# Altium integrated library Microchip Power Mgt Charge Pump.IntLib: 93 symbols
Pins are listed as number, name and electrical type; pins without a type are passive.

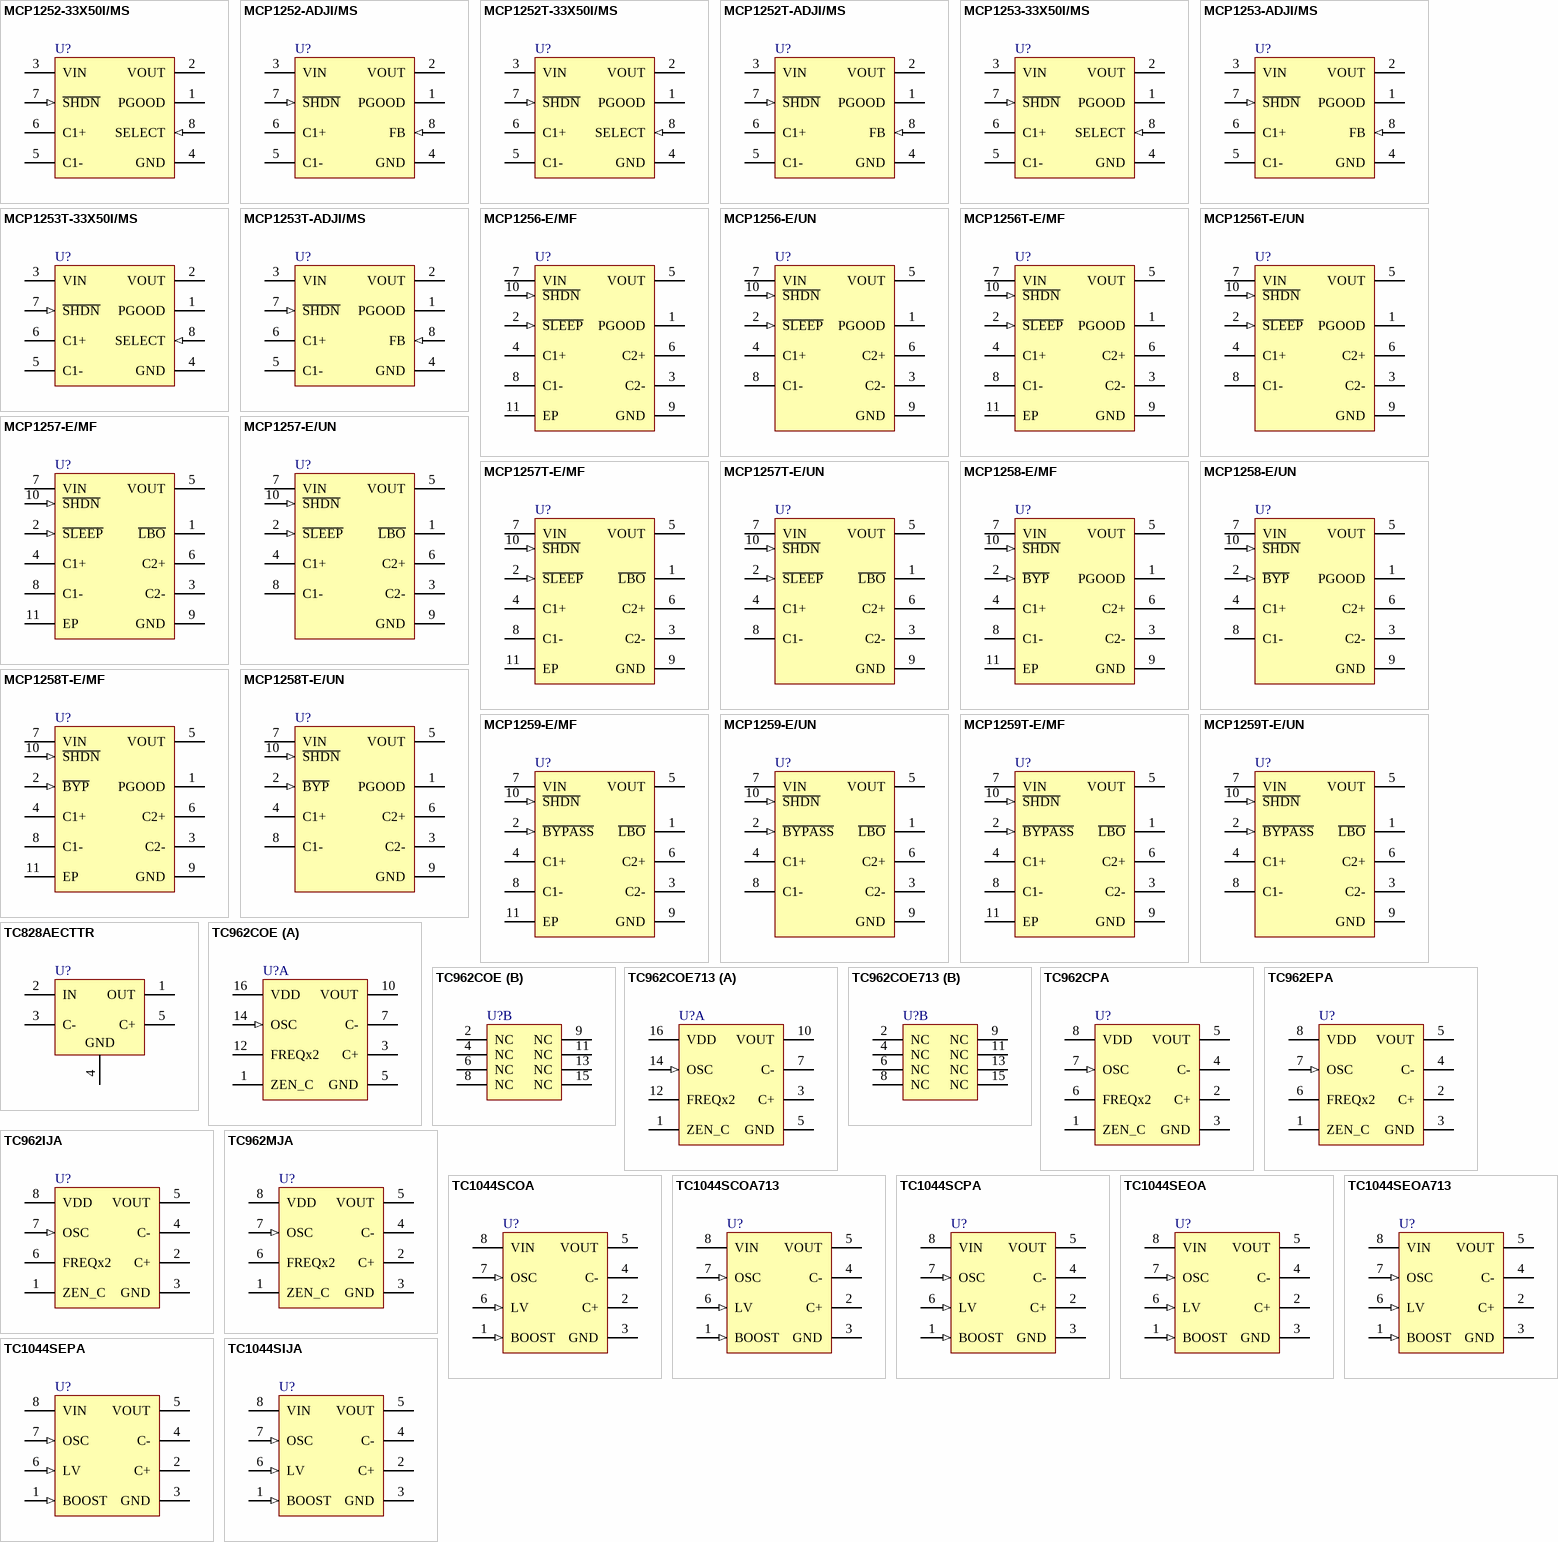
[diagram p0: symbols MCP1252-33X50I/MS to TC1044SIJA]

## MCP1252-33X50I/MS
designator U?
Low Noise, Positive-Regulated Charge Pump, 650kHz, Fixed Output, 8-Pin MSOP, Industrial Temperature
footprint MSOP-MS8_N (TSOP, 8-Leads, Body 3x3mm, Pitch 0.65mm, IPC Medium Density)
footprint MSOP-MS8_L (TSOP, 8-Leads, Body 3x3mm, Pitch 0.65mm, IPC High Density)
footprint MSOP-MS8_M (TSOP, 8-Leads, Body 3x3mm, Pitch 0.65mm, IPC Low Density)
pins: 1 PGOOD (oc), 2 VOUT (power), 3 VIN (power), 4 GND (power), 5 C1-, 6 C1+, 7 ~{SHDN} (in), 8 SELECT (in)

## MCP1252-ADJI/MS
designator U?
Low Noise, Positive-Regulated Charge Pump, 650kHz, Adjustable Output, 8-Pin MSOP, Industrial Temperature
footprint MSOP-MS8_N (TSOP, 8-Leads, Body 3x3mm, Pitch 0.65mm, IPC Medium Density)
footprint MSOP-MS8_L (TSOP, 8-Leads, Body 3x3mm, Pitch 0.65mm, IPC High Density)
footprint MSOP-MS8_M (TSOP, 8-Leads, Body 3x3mm, Pitch 0.65mm, IPC Low Density)
pins: 1 PGOOD (oc), 2 VOUT (power), 3 VIN (power), 4 GND (power), 5 C1-, 6 C1+, 7 ~{SHDN} (in), 8 FB (in)

## MCP1252T-33X50I/MS
designator U?
Low Noise, Positive-Regulated Charge Pump, 650kHz, Fixed Output, 8-Pin MSOP, Industrial Temperature, Tape and Reel
footprint MSOP-MS8_N (TSOP, 8-Leads, Body 3x3mm, Pitch 0.65mm, IPC Medium Density)
footprint MSOP-MS8_L (TSOP, 8-Leads, Body 3x3mm, Pitch 0.65mm, IPC High Density)
footprint MSOP-MS8_M (TSOP, 8-Leads, Body 3x3mm, Pitch 0.65mm, IPC Low Density)
pins: 1 PGOOD (oc), 2 VOUT (power), 3 VIN (power), 4 GND (power), 5 C1-, 6 C1+, 7 ~{SHDN} (in), 8 SELECT (in)

## MCP1252T-ADJI/MS
designator U?
Low Noise, Positive-Regulated Charge Pump, 650kHz, Adjustable Output, 8-Pin MSOP, Industrial Temperature, Tape and Reel
footprint MSOP-MS8_N (TSOP, 8-Leads, Body 3x3mm, Pitch 0.65mm, IPC Medium Density)
footprint MSOP-MS8_L (TSOP, 8-Leads, Body 3x3mm, Pitch 0.65mm, IPC High Density)
footprint MSOP-MS8_M (TSOP, 8-Leads, Body 3x3mm, Pitch 0.65mm, IPC Low Density)
pins: 1 PGOOD (oc), 2 VOUT (power), 3 VIN (power), 4 GND (power), 5 C1-, 6 C1+, 7 ~{SHDN} (in), 8 FB (in)

## MCP1253-33X50I/MS
designator U?
Low Noise, Positive-Regulated Charge Pump, 1MHz, Fixed Output, 8-Pin MSOP, Industrial Temperature
footprint MSOP-MS8_N (TSOP, 8-Leads, Body 3x3mm, Pitch 0.65mm, IPC Medium Density)
footprint MSOP-MS8_L (TSOP, 8-Leads, Body 3x3mm, Pitch 0.65mm, IPC High Density)
footprint MSOP-MS8_M (TSOP, 8-Leads, Body 3x3mm, Pitch 0.65mm, IPC Low Density)
pins: 1 PGOOD (oc), 2 VOUT (power), 3 VIN (power), 4 GND (power), 5 C1-, 6 C1+, 7 ~{SHDN} (in), 8 SELECT (in)

## MCP1253-ADJI/MS
designator U?
Low Noise, Positive-Regulated Charge Pump, 1MHz, Adjustable Output, 8-Pin MSOP, Industrial Temperature
footprint MSOP-MS8_N (TSOP, 8-Leads, Body 3x3mm, Pitch 0.65mm, IPC Medium Density)
footprint MSOP-MS8_L (TSOP, 8-Leads, Body 3x3mm, Pitch 0.65mm, IPC High Density)
footprint MSOP-MS8_M (TSOP, 8-Leads, Body 3x3mm, Pitch 0.65mm, IPC Low Density)
pins: 1 PGOOD (oc), 2 VOUT (power), 3 VIN (power), 4 GND (power), 5 C1-, 6 C1+, 7 ~{SHDN} (in), 8 FB (in)

## MCP1253T-33X50I/MS
designator U?
Low Noise, Positive-Regulated Charge Pump, 1MHz, Fixed Output, 8-Pin MSOP, Industrial Temperature, Tape and Reel
footprint MSOP-MS8_N (TSOP, 8-Leads, Body 3x3mm, Pitch 0.65mm, IPC Medium Density)
footprint MSOP-MS8_L (TSOP, 8-Leads, Body 3x3mm, Pitch 0.65mm, IPC High Density)
footprint MSOP-MS8_M (TSOP, 8-Leads, Body 3x3mm, Pitch 0.65mm, IPC Low Density)
pins: 1 PGOOD (oc), 2 VOUT (power), 3 VIN (power), 4 GND (power), 5 C1-, 6 C1+, 7 ~{SHDN} (in), 8 SELECT (in)

## MCP1253T-ADJI/MS
designator U?
Low Noise, Positive-Regulated Charge Pump, 1MHz, Adjustable Output, 8-Pin MSOP, Industrial Temperature, Tape and Reel
footprint MSOP-MS8_N (TSOP, 8-Leads, Body 3x3mm, Pitch 0.65mm, IPC Medium Density)
footprint MSOP-MS8_L (TSOP, 8-Leads, Body 3x3mm, Pitch 0.65mm, IPC High Density)
footprint MSOP-MS8_M (TSOP, 8-Leads, Body 3x3mm, Pitch 0.65mm, IPC Low Density)
pins: 1 PGOOD (oc), 2 VOUT (power), 3 VIN (power), 4 GND (power), 5 C1-, 6 C1+, 7 ~{SHDN} (in), 8 FB (in)

## MCP1256-E/MF
designator U?
Regulated 3.3V, Low-Ripple Charge Pump with SLEEP Mode & Power-Good Output, 10-Pin DFN, Extended Temperature
footprint DFN-MF10 (SON, 10-Leads, Body 3x3mm, Pitch 0.5mm, Microchip Recommended)
pins: 1 PGOOD (oc), 2 ~{SLEEP} (in), 3 C2-, 4 C1+, 5 VOUT (power), 6 C2+, 7 VIN (power), 8 C1-, 9 GND (power), 10 ~{SHDN} (in), 11 EP (power)

## MCP1256-E/UN
designator U?
Regulated 3.3V, Low-Ripple Charge Pump with SLEEP Mode & Power-Good Output, 10-Pin MSOP, Extended Temperature
footprint MSOP-UN10_N (TSSOP, 10-Leads, Body 3x3mm, Pitch 0.5mm, IPC Medium Density)
footprint MSOP-UN10_L (TSSOP, 10-Leads, Body 3x3mm, Pitch 0.5mm, IPC High Density)
footprint MSOP-UN10_M (TSSOP, 10-Leads, Body 3x3mm, Pitch 0.5mm, IPC Low Density)
pins: 1 PGOOD (oc), 2 ~{SLEEP} (in), 3 C2-, 4 C1+, 5 VOUT (power), 6 C2+, 7 VIN (power), 8 C1-, 9 GND (power), 10 ~{SHDN} (in)

## MCP1256T-E/MF
designator U?
Regulated 3.3V, Low-Ripple Charge Pump with SLEEP Mode & Power-Good Output, 10-Pin DFN, Extended Temperature, Tape and Reel
footprint DFN-MF10 (SON, 10-Leads, Body 3x3mm, Pitch 0.5mm, Microchip Recommended)
pins: 1 PGOOD (oc), 2 ~{SLEEP} (in), 3 C2-, 4 C1+, 5 VOUT (power), 6 C2+, 7 VIN (power), 8 C1-, 9 GND (power), 10 ~{SHDN} (in), 11 EP (power)

## MCP1256T-E/UN
designator U?
Regulated 3.3V, Low-Ripple Charge Pump with SLEEP Mode & Power-Good Output, 10-Pin MSOP, Extended Temperature, Tape and Reel
footprint MSOP-UN10_N (TSSOP, 10-Leads, Body 3x3mm, Pitch 0.5mm, IPC Medium Density)
footprint MSOP-UN10_L (TSSOP, 10-Leads, Body 3x3mm, Pitch 0.5mm, IPC High Density)
footprint MSOP-UN10_M (TSSOP, 10-Leads, Body 3x3mm, Pitch 0.5mm, IPC Low Density)
pins: 1 PGOOD (oc), 2 ~{SLEEP} (in), 3 C2-, 4 C1+, 5 VOUT (power), 6 C2+, 7 VIN (power), 8 C1-, 9 GND (power), 10 ~{SHDN} (in)

## MCP1257-E/MF
designator U?
Regulated 3.3V, Low-Ripple Charge Pump with SLEEP Mode & Low-Battery Output, 10-Pin DFN, Extended Temperature
footprint DFN-MF10 (SON, 10-Leads, Body 3x3mm, Pitch 0.5mm, Microchip Recommended)
pins: 1 ~{LBO} (oc), 2 ~{SLEEP} (in), 3 C2-, 4 C1+, 5 VOUT (power), 6 C2+, 7 VIN (power), 8 C1-, 9 GND (power), 10 ~{SHDN} (in), 11 EP (power)

## MCP1257-E/UN
designator U?
Regulated 3.3V, Low-Ripple Charge Pump with SLEEP Mode & Low-Battery Output, 10-Pin MSOP, Extended Temperature
footprint MSOP-UN10_N (TSSOP, 10-Leads, Body 3x3mm, Pitch 0.5mm, IPC Medium Density)
footprint MSOP-UN10_L (TSSOP, 10-Leads, Body 3x3mm, Pitch 0.5mm, IPC High Density)
footprint MSOP-UN10_M (TSSOP, 10-Leads, Body 3x3mm, Pitch 0.5mm, IPC Low Density)
pins: 1 ~{LBO} (oc), 2 ~{SLEEP} (in), 3 C2-, 4 C1+, 5 VOUT (power), 6 C2+, 7 VIN (power), 8 C1-, 9 GND (power), 10 ~{SHDN} (in)

## MCP1257T-E/MF
designator U?
Regulated 3.3V, Low-Ripple Charge Pump with SLEEP Mode & Low-Battery Output, 10-Pin DFN, Extended Temperature, Tape and Reel
footprint DFN-MF10 (SON, 10-Leads, Body 3x3mm, Pitch 0.5mm, Microchip Recommended)
pins: 1 ~{LBO} (oc), 2 ~{SLEEP} (in), 3 C2-, 4 C1+, 5 VOUT (power), 6 C2+, 7 VIN (power), 8 C1-, 9 GND (power), 10 ~{SHDN} (in), 11 EP (power)

## MCP1257T-E/UN
designator U?
Regulated 3.3V, Low-Ripple Charge Pump with SLEEP Mode & Low-Battery Output, 10-Pin MSOP, Extended Temperature, Tape and Reel
footprint MSOP-UN10_N (TSSOP, 10-Leads, Body 3x3mm, Pitch 0.5mm, IPC Medium Density)
footprint MSOP-UN10_L (TSSOP, 10-Leads, Body 3x3mm, Pitch 0.5mm, IPC High Density)
footprint MSOP-UN10_M (TSSOP, 10-Leads, Body 3x3mm, Pitch 0.5mm, IPC Low Density)
pins: 1 ~{LBO} (oc), 2 ~{SLEEP} (in), 3 C2-, 4 C1+, 5 VOUT (power), 6 C2+, 7 VIN (power), 8 C1-, 9 GND (power), 10 ~{SHDN} (in)

## MCP1258-E/MF
designator U?
Regulated 3.3V, Low-Ripple Charge Pump with BYPASS Mode & Power-Good Output, 10-Pin DFN, Extended Temperature
footprint DFN-MF10 (SON, 10-Leads, Body 3x3mm, Pitch 0.5mm, Microchip Recommended)
pins: 1 PGOOD (oc), 2 ~{BYP} (in), 3 C2-, 4 C1+, 5 VOUT (power), 6 C2+, 7 VIN (power), 8 C1-, 9 GND (power), 10 ~{SHDN} (in), 11 EP (power)

## MCP1258-E/UN
designator U?
Regulated 3.3V, Low-Ripple Charge Pump with BYPASS Mode & Power-Good Output, 10-Pin MSOP, Extended Temperature
footprint MSOP-UN10_N (TSSOP, 10-Leads, Body 3x3mm, Pitch 0.5mm, IPC Medium Density)
footprint MSOP-UN10_L (TSSOP, 10-Leads, Body 3x3mm, Pitch 0.5mm, IPC High Density)
footprint MSOP-UN10_M (TSSOP, 10-Leads, Body 3x3mm, Pitch 0.5mm, IPC Low Density)
pins: 1 PGOOD (oc), 2 ~{BYP} (in), 3 C2-, 4 C1+, 5 VOUT (power), 6 C2+, 7 VIN (power), 8 C1-, 9 GND (power), 10 ~{SHDN} (in)

## MCP1258T-E/MF
designator U?
Regulated 3.3V, Low-Ripple Charge Pump with BYPASS Mode & Power-Good Output, 10-Pin DFN, Extended Temperature, Tape and Reel
footprint DFN-MF10 (SON, 10-Leads, Body 3x3mm, Pitch 0.5mm, Microchip Recommended)
pins: 1 PGOOD (oc), 2 ~{BYP} (in), 3 C2-, 4 C1+, 5 VOUT (power), 6 C2+, 7 VIN (power), 8 C1-, 9 GND (power), 10 ~{SHDN} (in), 11 EP (power)

## MCP1258T-E/UN
designator U?
Regulated 3.3V, Low-Ripple Charge Pump with BYPASS Mode & Power-Good Output, 10-Pin MSOP, Extended Temperature, Tape and Reel
footprint MSOP-UN10_N (TSSOP, 10-Leads, Body 3x3mm, Pitch 0.5mm, IPC Medium Density)
footprint MSOP-UN10_L (TSSOP, 10-Leads, Body 3x3mm, Pitch 0.5mm, IPC High Density)
footprint MSOP-UN10_M (TSSOP, 10-Leads, Body 3x3mm, Pitch 0.5mm, IPC Low Density)
pins: 1 PGOOD (oc), 2 ~{BYP} (in), 3 C2-, 4 C1+, 5 VOUT (power), 6 C2+, 7 VIN (power), 8 C1-, 9 GND (power), 10 ~{SHDN} (in)

## MCP1259-E/MF
designator U?
Regulated 3.3V, Low-Ripple Charge Pump with BYPASS Mode & Low-Battery Output, 10-Pin DFN, Extended Temperature
footprint DFN-MF10 (SON, 10-Leads, Body 3x3mm, Pitch 0.5mm, Microchip Recommended)
pins: 1 ~{LBO} (oc), 2 ~{BYPASS} (in), 3 C2-, 4 C1+, 5 VOUT (power), 6 C2+, 7 VIN (power), 8 C1-, 9 GND (power), 10 ~{SHDN} (in), 11 EP (power)

## MCP1259-E/UN
designator U?
Regulated 3.3V, Low-Ripple Charge Pump with BYPASS Mode & Low-Battery Output, 10-Pin MSOP, Extended Temperature
footprint MSOP-UN10_N (TSSOP, 10-Leads, Body 3x3mm, Pitch 0.5mm, IPC Medium Density)
footprint MSOP-UN10_L (TSSOP, 10-Leads, Body 3x3mm, Pitch 0.5mm, IPC High Density)
footprint MSOP-UN10_M (TSSOP, 10-Leads, Body 3x3mm, Pitch 0.5mm, IPC Low Density)
pins: 1 ~{LBO} (oc), 2 ~{BYPASS} (in), 3 C2-, 4 C1+, 5 VOUT (power), 6 C2+, 7 VIN (power), 8 C1-, 9 GND (power), 10 ~{SHDN} (in)

## MCP1259T-E/MF
designator U?
Regulated 3.3V, Low-Ripple Charge Pump with BYPASS Mode & Low-Battery Output, 10-Pin DFN, Extended Temperature, Tape and Reel
footprint DFN-MF10 (SON, 10-Leads, Body 3x3mm, Pitch 0.5mm, Microchip Recommended)
pins: 1 ~{LBO} (oc), 2 ~{BYPASS} (in), 3 C2-, 4 C1+, 5 VOUT (power), 6 C2+, 7 VIN (power), 8 C1-, 9 GND (power), 10 ~{SHDN} (in), 11 EP (power)

## MCP1259T-E/UN
designator U?
Regulated 3.3V, Low-Ripple Charge Pump with BYPASS Mode & Low-Battery Output, 10-Pin MSOP, Extended Temperature, Tape and Reel
footprint MSOP-UN10_N (TSSOP, 10-Leads, Body 3x3mm, Pitch 0.5mm, IPC Medium Density)
footprint MSOP-UN10_L (TSSOP, 10-Leads, Body 3x3mm, Pitch 0.5mm, IPC High Density)
footprint MSOP-UN10_M (TSSOP, 10-Leads, Body 3x3mm, Pitch 0.5mm, IPC Low Density)
pins: 1 ~{LBO} (oc), 2 ~{BYPASS} (in), 3 C2-, 4 C1+, 5 VOUT (power), 6 C2+, 7 VIN (power), 8 C1-, 9 GND (power), 10 ~{SHDN} (in)

## TC828AECTTR
designator U?
50µA Switched Capacitor Voltage Converter, 5-Pin SOT-23, Industrial Temperature, Tape and Reel
footprint SOT-23-CT5_N (SOT23, 5-Leads, Body 2.9x1.6mm, Pitch 0.95mm, Lead Span 2.7mm, IPC Medium Density)
footprint SOT-23-CT5_L (SOT23, 5-Leads, Body 2.9x1.6mm, Pitch 0.95mm, Lead Span 2.7mm, IPC High Density)
footprint SOT-23-CT5_M (SOT23, 5-Leads, Body 2.9x1.6mm, Pitch 0.95mm, Lead Span 2.7mm, IPC Low Density)
pins: 1 OUT (power), 2 IN (power), 3 C-, 4 GND (power), 5 C+

## TC962COE
designator U?
80mA Charge Pump DC-to-DC Converter, 12kHz, 24kHz, 16-Pin SOIC 300mil, Commercial Temperature
footprint SOIC-OE16_N (SOIC, 16-Leads, Body 10.3x7.5mm, Pitch 1.27mm, IPC Medium Density)
footprint SOIC-OE16_L (SOIC, 16-Leads, Body 10.3x7.5mm, Pitch 1.27mm, IPC High Density)
footprint SOIC-OE16_M (SOIC, 16-Leads, Body 10.3x7.5mm, Pitch 1.27mm, IPC Low Density)
part A pins: 1 ZEN_C, 3 C+, 5 GND (power), 7 C-, 10 VOUT (power), 12 FREQx2, 14 OSC (in), 16 VDD (power)
part B pins: 2 NC, 4 NC, 6 NC, 8 NC, 9 NC, 11 NC, 13 NC, 15 NC

## TC962COE713
designator U?
80mA Charge Pump DC-to-DC Converter, 12kHz, 24kHz, 16-Pin SOIC 300mil, Commercial Temperature, Tape and Reel
footprint SOIC-OE16_N (SOIC, 16-Leads, Body 10.3x7.5mm, Pitch 1.27mm, IPC Medium Density)
footprint SOIC-OE16_L (SOIC, 16-Leads, Body 10.3x7.5mm, Pitch 1.27mm, IPC High Density)
footprint SOIC-OE16_M (SOIC, 16-Leads, Body 10.3x7.5mm, Pitch 1.27mm, IPC Low Density)
part A pins: 1 ZEN_C, 3 C+, 5 GND (power), 7 C-, 10 VOUT (power), 12 FREQx2, 14 OSC (in), 16 VDD (power)
part B pins: 2 NC, 4 NC, 6 NC, 8 NC, 9 NC, 11 NC, 13 NC, 15 NC

## TC962CPA
designator U?
80mA Charge Pump DC-to-DC Converter, 12kHz, 24kHz, 8-Pin PDIP, Commercial Temperature
footprint PDIP300-PA8 (DIP, 8-Leads, Row Spacing 7.62mm, Pitch 2.54mm, Body 9.5x6.6mm)
pins: 1 ZEN_C, 2 C+, 3 GND (power), 4 C-, 5 VOUT (power), 6 FREQx2, 7 OSC (in), 8 VDD (power)

## TC962EPA
designator U?
80mA Charge Pump DC-to-DC Converter, 12kHz, 24kHz, 8-Pin PDIP, Industrial Temperature
footprint PDIP300-PA8 (DIP, 8-Leads, Row Spacing 7.62mm, Pitch 2.54mm, Body 9.5x6.6mm)
pins: 1 ZEN_C, 2 C+, 3 GND (power), 4 C-, 5 VOUT (power), 6 FREQx2, 7 OSC (in), 8 VDD (power)

## TC962IJA
designator U?
80mA Charge Pump DC-to-DC Converter, 12kHz, 24kHz, 8-Pin CERDIP 300mil, -25ºC to +85ºC; ComponentAvailability: Unknown. Contact manufacturer to determine status.
footprint CERDIP300-JA8 (DIP, 8-Leads, Row Spacing 7.62mm, Pitch 2.54mm, Body 9.8x6.7mm)
pins: 1 ZEN_C, 2 C+, 3 GND (power), 4 C-, 5 VOUT (power), 6 FREQx2, 7 OSC (in), 8 VDD (power)

## TC962MJA
designator U?
80mA Charge Pump DC-to-DC Converter, 12kHz, 24kHz, 8-Pin CERDIP 300mil, -55ºC to +125ºC; ComponentAvailability: Unknown. Contact manufacturer to determine status.
footprint CERDIP300-JA8 (DIP, 8-Leads, Row Spacing 7.62mm, Pitch 2.54mm, Body 9.8x6.7mm)
pins: 1 ZEN_C, 2 C+, 3 GND (power), 4 C-, 5 VOUT (power), 6 FREQx2, 7 OSC (in), 8 VDD (power)

## TC1044SCOA
designator U?
Charge Pump DC-TO-DC Voltage Converter, 8-Pin SOIC 150mil, Commercial Temperature
footprint SOIC-OA8_N (SOIC, 8-Leads, Body 4.9x3.9mm, Pitch 1.27mm, IPC Medium Density)
footprint SOIC-OA8_L (SOIC, 8-Leads, Body 4.9x3.9mm, Pitch 1.27mm, IPC High Density)
footprint SOIC-OA8_M (SOIC, 8-Leads, Body 4.9x3.9mm, Pitch 1.27mm, IPC Low Density)
pins: 1 BOOST (in), 2 C+, 3 GND (power), 4 C-, 5 VOUT (power), 6 LV (in), 7 OSC (in), 8 VIN (power)

## TC1044SCOA713
designator U?
Charge Pump DC-TO-DC Voltage Converter, 8-Pin SOIC 150mil, Commercial Temperature, Tape and Reel
footprint SOIC-OA8_N (SOIC, 8-Leads, Body 4.9x3.9mm, Pitch 1.27mm, IPC Medium Density)
footprint SOIC-OA8_L (SOIC, 8-Leads, Body 4.9x3.9mm, Pitch 1.27mm, IPC High Density)
footprint SOIC-OA8_M (SOIC, 8-Leads, Body 4.9x3.9mm, Pitch 1.27mm, IPC Low Density)
pins: 1 BOOST (in), 2 C+, 3 GND (power), 4 C-, 5 VOUT (power), 6 LV (in), 7 OSC (in), 8 VIN (power)

## TC1044SCPA
designator U?
Charge Pump DC-TO-DC Voltage Converter, 8-Pin PDIP, Commercial Temperature
footprint PDIP300-PA8 (DIP, 8-Leads, Row Spacing 7.62mm, Pitch 2.54mm, Body 9.5x6.6mm)
pins: 1 BOOST (in), 2 C+, 3 GND (power), 4 C-, 5 VOUT (power), 6 LV (in), 7 OSC (in), 8 VIN (power)

## TC1044SEOA
designator U?
Charge Pump DC-TO-DC Voltage Converter, 8-Pin SOIC 150mil, Industrial Temperature
footprint SOIC-OA8_N (SOIC, 8-Leads, Body 4.9x3.9mm, Pitch 1.27mm, IPC Medium Density)
footprint SOIC-OA8_L (SOIC, 8-Leads, Body 4.9x3.9mm, Pitch 1.27mm, IPC High Density)
footprint SOIC-OA8_M (SOIC, 8-Leads, Body 4.9x3.9mm, Pitch 1.27mm, IPC Low Density)
pins: 1 BOOST (in), 2 C+, 3 GND (power), 4 C-, 5 VOUT (power), 6 LV (in), 7 OSC (in), 8 VIN (power)

## TC1044SEOA713
designator U?
Charge Pump DC-TO-DC Voltage Converter, 8-Pin SOIC 150mil, Industrial Temperature, Tape and Reel
footprint SOIC-OA8_N (SOIC, 8-Leads, Body 4.9x3.9mm, Pitch 1.27mm, IPC Medium Density)
footprint SOIC-OA8_L (SOIC, 8-Leads, Body 4.9x3.9mm, Pitch 1.27mm, IPC High Density)
footprint SOIC-OA8_M (SOIC, 8-Leads, Body 4.9x3.9mm, Pitch 1.27mm, IPC Low Density)
pins: 1 BOOST (in), 2 C+, 3 GND (power), 4 C-, 5 VOUT (power), 6 LV (in), 7 OSC (in), 8 VIN (power)

## TC1044SEPA
designator U?
Charge Pump DC-TO-DC Voltage Converter, 8-Pin PDIP, Industrial Temperature
footprint PDIP300-PA8 (DIP, 8-Leads, Row Spacing 7.62mm, Pitch 2.54mm, Body 9.5x6.6mm)
pins: 1 BOOST (in), 2 C+, 3 GND (power), 4 C-, 5 VOUT (power), 6 LV (in), 7 OSC (in), 8 VIN (power)

## TC1044SIJA
designator U?
Charge Pump DC-TO-DC Voltage Converter, 8-Pin CERDIP 300mil, -25ºC to +85ºC; ComponentAvailability: Unknown. Contact manufacturer to determine status.
footprint CERDIP300-JA8 (DIP, 8-Leads, Row Spacing 7.62mm, Pitch 2.54mm, Body 9.8x6.7mm)
pins: 1 BOOST (in), 2 C+, 3 GND (power), 4 C-, 5 VOUT (power), 6 LV (in), 7 OSC (in), 8 VIN (power)

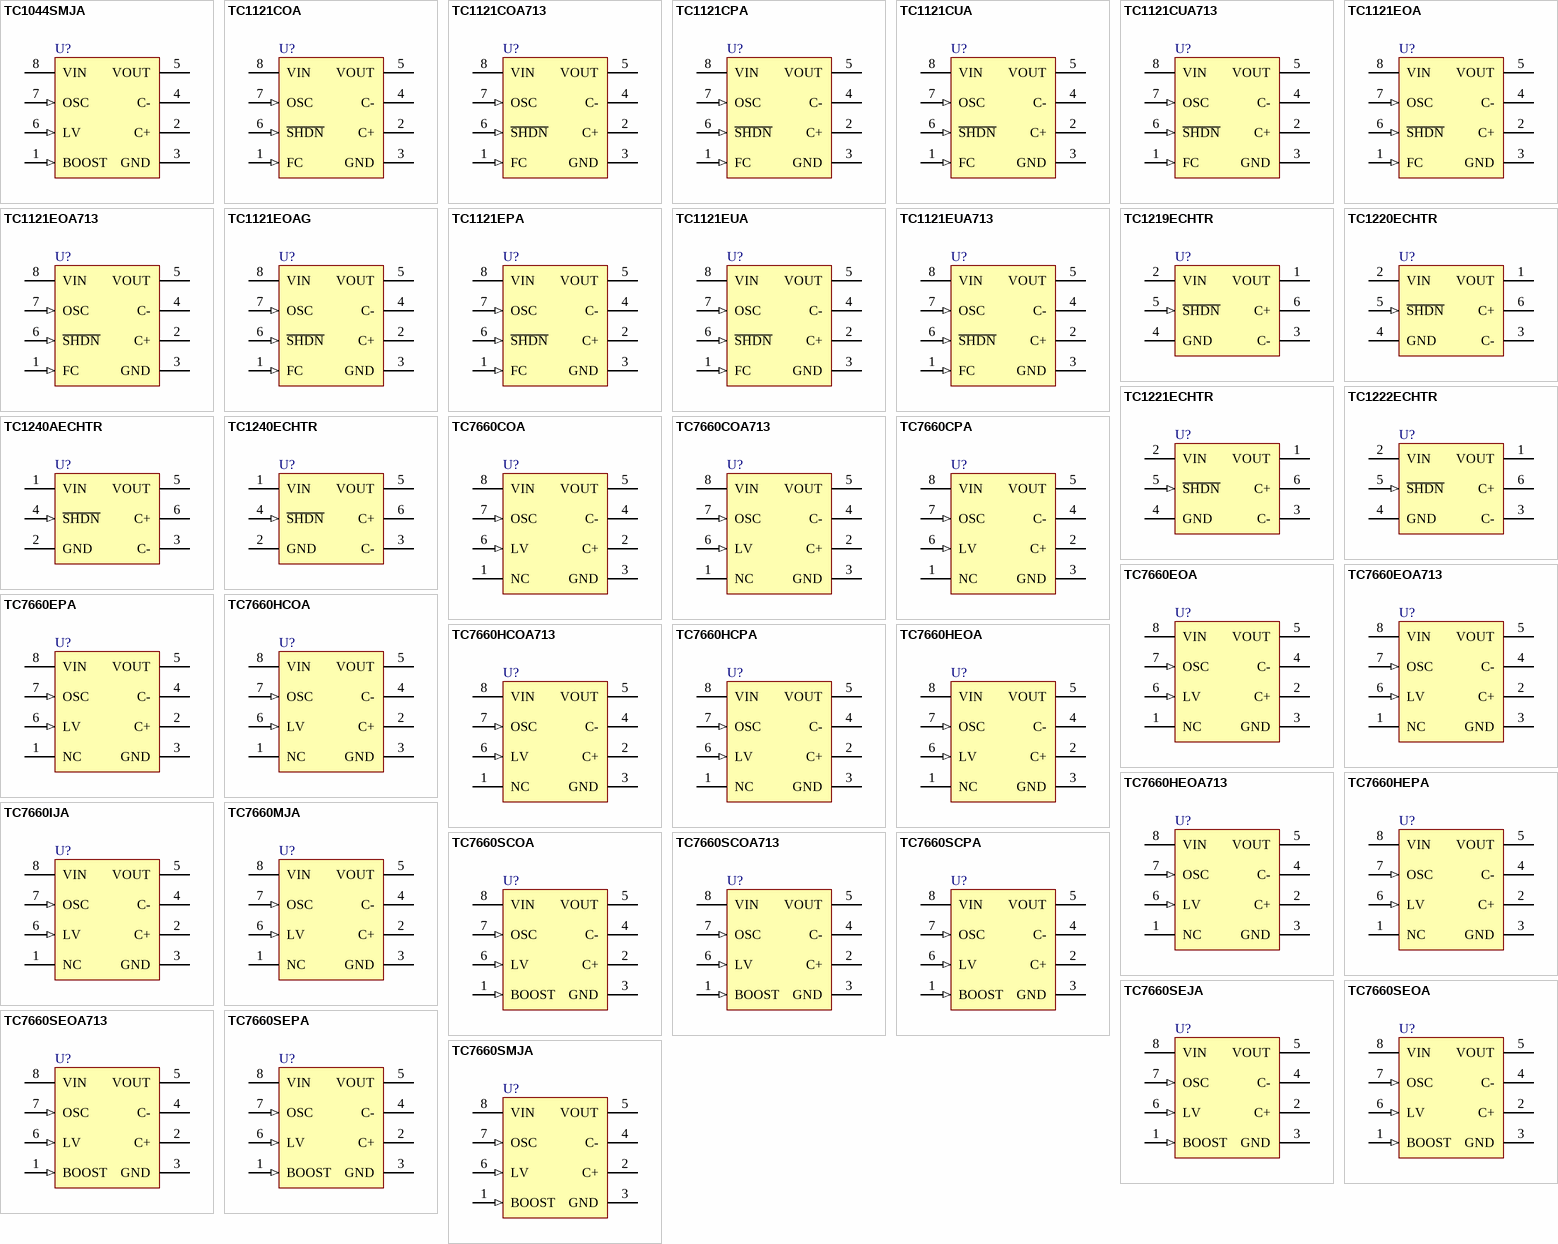
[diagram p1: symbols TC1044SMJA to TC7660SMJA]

## TC1044SMJA
designator U?
Charge Pump DC-TO-DC Voltage Converter, 8-Pin CERDIP 300mil, -55ºC to +125ºC; ComponentAvailability: Unknown. Contact manufacturer to determine status.
footprint CERDIP300-JA8 (DIP, 8-Leads, Row Spacing 7.62mm, Pitch 2.54mm, Body 9.8x6.7mm)
pins: 1 BOOST (in), 2 C+, 3 GND (power), 4 C-, 5 VOUT (power), 6 LV (in), 7 OSC (in), 8 VIN (power)

## TC1121COA
designator U?
100mA Charge Pump Voltage Converter with Shutdown, 8-Pin SOIC 150mil, Commercial Temperature
footprint SOIC-OA8_N (SOIC, 8-Leads, Body 4.9x3.9mm, Pitch 1.27mm, IPC Medium Density)
footprint SOIC-OA8_L (SOIC, 8-Leads, Body 4.9x3.9mm, Pitch 1.27mm, IPC High Density)
footprint SOIC-OA8_M (SOIC, 8-Leads, Body 4.9x3.9mm, Pitch 1.27mm, IPC Low Density)
pins: 1 FC (in), 2 C+, 3 GND (power), 4 C-, 5 VOUT (power), 6 ~{SHDN} (in), 7 OSC (in), 8 VIN (power)

## TC1121COA713
designator U?
100mA Charge Pump Voltage Converter with Shutdown, 8-Pin SOIC 150mil, Commercial Temperature, Tape and Reel
footprint SOIC-OA8_N (SOIC, 8-Leads, Body 4.9x3.9mm, Pitch 1.27mm, IPC Medium Density)
footprint SOIC-OA8_L (SOIC, 8-Leads, Body 4.9x3.9mm, Pitch 1.27mm, IPC High Density)
footprint SOIC-OA8_M (SOIC, 8-Leads, Body 4.9x3.9mm, Pitch 1.27mm, IPC Low Density)
pins: 1 FC (in), 2 C+, 3 GND (power), 4 C-, 5 VOUT (power), 6 ~{SHDN} (in), 7 OSC (in), 8 VIN (power)

## TC1121CPA
designator U?
100mA Charge Pump Voltage Converter with Shutdown, 8-Pin PDIP, Commercial Temperature
footprint PDIP300-PA8 (DIP, 8-Leads, Row Spacing 7.62mm, Pitch 2.54mm, Body 9.5x6.6mm)
pins: 1 FC (in), 2 C+, 3 GND (power), 4 C-, 5 VOUT (power), 6 ~{SHDN} (in), 7 OSC (in), 8 VIN (power)

## TC1121CUA
designator U?
100mA Charge Pump Voltage Converter with Shutdown, 8-Pin MSOP, Commercial Temperature
footprint MSOP-UA8_N (TSOP, 8-Leads, Body 3x3mm, Pitch 0.65mm, IPC Medium Density)
footprint MSOP-UA8_L (TSOP, 8-Leads, Body 3x3mm, Pitch 0.65mm, IPC High Density)
footprint MSOP-UA8_M (TSOP, 8-Leads, Body 3x3mm, Pitch 0.65mm, IPC Low Density)
pins: 1 FC (in), 2 C+, 3 GND (power), 4 C-, 5 VOUT (power), 6 ~{SHDN} (in), 7 OSC (in), 8 VIN (power)

## TC1121CUA713
designator U?
100mA Charge Pump Voltage Converter with Shutdown, 8-Pin MSOP, Commercial Temperature, Tape and Reel
footprint MSOP-UA8_N (TSOP, 8-Leads, Body 3x3mm, Pitch 0.65mm, IPC Medium Density)
footprint MSOP-UA8_L (TSOP, 8-Leads, Body 3x3mm, Pitch 0.65mm, IPC High Density)
footprint MSOP-UA8_M (TSOP, 8-Leads, Body 3x3mm, Pitch 0.65mm, IPC Low Density)
pins: 1 FC (in), 2 C+, 3 GND (power), 4 C-, 5 VOUT (power), 6 ~{SHDN} (in), 7 OSC (in), 8 VIN (power)

## TC1121EOA
designator U?
100mA Charge Pump Voltage Converter with Shutdown, 8-Pin SOIC 150mil, Industrial Temperature
footprint SOIC-OA8_N (SOIC, 8-Leads, Body 4.9x3.9mm, Pitch 1.27mm, IPC Medium Density)
footprint SOIC-OA8_L (SOIC, 8-Leads, Body 4.9x3.9mm, Pitch 1.27mm, IPC High Density)
footprint SOIC-OA8_M (SOIC, 8-Leads, Body 4.9x3.9mm, Pitch 1.27mm, IPC Low Density)
pins: 1 FC (in), 2 C+, 3 GND (power), 4 C-, 5 VOUT (power), 6 ~{SHDN} (in), 7 OSC (in), 8 VIN (power)

## TC1121EOA713
designator U?
100mA Charge Pump Voltage Converter with Shutdown, 8-Pin SOIC 150mil, Industrial Temperature, Tape and Reel
footprint SOIC-OA8_N (SOIC, 8-Leads, Body 4.9x3.9mm, Pitch 1.27mm, IPC Medium Density)
footprint SOIC-OA8_L (SOIC, 8-Leads, Body 4.9x3.9mm, Pitch 1.27mm, IPC High Density)
footprint SOIC-OA8_M (SOIC, 8-Leads, Body 4.9x3.9mm, Pitch 1.27mm, IPC Low Density)
pins: 1 FC (in), 2 C+, 3 GND (power), 4 C-, 5 VOUT (power), 6 ~{SHDN} (in), 7 OSC (in), 8 VIN (power)

## TC1121EOAG
designator U?
100mA Charge Pump Voltage Converter with Shutdown, 8-Pin SOIC 150mil, Industrial Temperature
footprint SOIC-OA8_N (SOIC, 8-Leads, Body 4.9x3.9mm, Pitch 1.27mm, IPC Medium Density)
footprint SOIC-OA8_L (SOIC, 8-Leads, Body 4.9x3.9mm, Pitch 1.27mm, IPC High Density)
footprint SOIC-OA8_M (SOIC, 8-Leads, Body 4.9x3.9mm, Pitch 1.27mm, IPC Low Density)
pins: 1 FC (in), 2 C+, 3 GND (power), 4 C-, 5 VOUT (power), 6 ~{SHDN} (in), 7 OSC (in), 8 VIN (power)

## TC1121EPA
designator U?
100mA Charge Pump Voltage Converter with Shutdown, 8-Pin PDIP, Industrial Temperature
footprint PDIP300-PA8 (DIP, 8-Leads, Row Spacing 7.62mm, Pitch 2.54mm, Body 9.5x6.6mm)
pins: 1 FC (in), 2 C+, 3 GND (power), 4 C-, 5 VOUT (power), 6 ~{SHDN} (in), 7 OSC (in), 8 VIN (power)

## TC1121EUA
designator U?
100mA Charge Pump Voltage Converter with Shutdown, 8-Pin MSOP, Industrial Temperature
footprint MSOP-UA8_N (TSOP, 8-Leads, Body 3x3mm, Pitch 0.65mm, IPC Medium Density)
footprint MSOP-UA8_L (TSOP, 8-Leads, Body 3x3mm, Pitch 0.65mm, IPC High Density)
footprint MSOP-UA8_M (TSOP, 8-Leads, Body 3x3mm, Pitch 0.65mm, IPC Low Density)
pins: 1 FC (in), 2 C+, 3 GND (power), 4 C-, 5 VOUT (power), 6 ~{SHDN} (in), 7 OSC (in), 8 VIN (power)

## TC1121EUA713
designator U?
100mA Charge Pump Voltage Converter with Shutdown, 8-Pin MSOP, Industrial Temperature, Tape and Reel
footprint MSOP-UA8_N (TSOP, 8-Leads, Body 3x3mm, Pitch 0.65mm, IPC Medium Density)
footprint MSOP-UA8_L (TSOP, 8-Leads, Body 3x3mm, Pitch 0.65mm, IPC High Density)
footprint MSOP-UA8_M (TSOP, 8-Leads, Body 3x3mm, Pitch 0.65mm, IPC Low Density)
pins: 1 FC (in), 2 C+, 3 GND (power), 4 C-, 5 VOUT (power), 6 ~{SHDN} (in), 7 OSC (in), 8 VIN (power)

## TC1219ECHTR
designator U?
Switched Capacitor Voltage Converter with Shutdown, 12kHz, 6-Pin SOT-23, Industrial Temperature, Tape and Reel
footprint SOT-23-CH6_N (SOT23, 6-Leads, Body 2.9x1.6mm, Pitch 0.95mm, Lead Span 2.7mm, IPC Medium Density)
footprint SOT-23-CH6_L (SOT23, 6-Leads, Body 2.9x1.6mm, Pitch 0.95mm, Lead Span 2.7mm, IPC High Density)
footprint SOT-23-CH6_M (SOT23, 6-Leads, Body 2.9x1.6mm, Pitch 0.95mm, Lead Span 2.7mm, IPC Low Density)
pins: 1 VOUT (power), 2 VIN (power), 3 C-, 4 GND (power), 5 ~{SHDN} (in), 6 C+

## TC1220ECHTR
designator U?
Switched Capacitor Voltage Converter with Shutdown, 35kHz, 6-Pin SOT-23, Industrial Temperature, Tape and Reel
footprint SOT-23-CH6_N (SOT23, 6-Leads, Body 2.9x1.6mm, Pitch 0.95mm, Lead Span 2.7mm, IPC Medium Density)
footprint SOT-23-CH6_L (SOT23, 6-Leads, Body 2.9x1.6mm, Pitch 0.95mm, Lead Span 2.7mm, IPC High Density)
footprint SOT-23-CH6_M (SOT23, 6-Leads, Body 2.9x1.6mm, Pitch 0.95mm, Lead Span 2.7mm, IPC Low Density)
pins: 1 VOUT (power), 2 VIN (power), 3 C-, 4 GND (power), 5 ~{SHDN} (in), 6 C+

## TC1221ECHTR
designator U?
Switched Capacitor Voltage Converter with Shutdown, 125kHz, 6-Pin SOT-23, Industrial Temperature, Tape and Reel
footprint SOT-23-CH6_N (SOT23, 6-Leads, Body 2.9x1.6mm, Pitch 0.95mm, Lead Span 2.7mm, IPC Medium Density)
footprint SOT-23-CH6_L (SOT23, 6-Leads, Body 2.9x1.6mm, Pitch 0.95mm, Lead Span 2.7mm, IPC High Density)
footprint SOT-23-CH6_M (SOT23, 6-Leads, Body 2.9x1.6mm, Pitch 0.95mm, Lead Span 2.7mm, IPC Low Density)
pins: 1 VOUT (power), 2 VIN (power), 3 C-, 4 GND (power), 5 ~{SHDN} (in), 6 C+

## TC1222ECHTR
designator U?
Switched Capacitor Voltage Converter with Shutdown, 750kHz, 6-Pin SOT-23, Industrial Temperature, Tape and Reel
footprint SOT-23-CH6_N (SOT23, 6-Leads, Body 2.9x1.6mm, Pitch 0.95mm, Lead Span 2.7mm, IPC Medium Density)
footprint SOT-23-CH6_L (SOT23, 6-Leads, Body 2.9x1.6mm, Pitch 0.95mm, Lead Span 2.7mm, IPC High Density)
footprint SOT-23-CH6_M (SOT23, 6-Leads, Body 2.9x1.6mm, Pitch 0.95mm, Lead Span 2.7mm, IPC Low Density)
pins: 1 VOUT (power), 2 VIN (power), 3 C-, 4 GND (power), 5 ~{SHDN} (in), 6 C+

## TC1240AECHTR
designator U?
Positive Doubling Charge Pumps with Shutdown, +2.5V to +5.5V, 6-Pin SOT-23, Industrial Temperature, Tape and Reel
footprint SOT-23-CH6_N (SOT23, 6-Leads, Body 2.9x1.6mm, Pitch 0.95mm, Lead Span 2.7mm, IPC Medium Density)
footprint SOT-23-CH6_L (SOT23, 6-Leads, Body 2.9x1.6mm, Pitch 0.95mm, Lead Span 2.7mm, IPC High Density)
footprint SOT-23-CH6_M (SOT23, 6-Leads, Body 2.9x1.6mm, Pitch 0.95mm, Lead Span 2.7mm, IPC Low Density)
pins: 1 VIN (power), 2 GND (power), 3 C-, 4 ~{SHDN} (in), 5 VOUT (power), 6 C+

## TC1240ECHTR
designator U?
Positive Doubling Charge Pumps with Shutdown, +2.5V to +4.0V, 6-Pin SOT-23, Industrial Temperature, Tape and Reel
footprint SOT-23-CH6_N (SOT23, 6-Leads, Body 2.9x1.6mm, Pitch 0.95mm, Lead Span 2.7mm, IPC Medium Density)
footprint SOT-23-CH6_L (SOT23, 6-Leads, Body 2.9x1.6mm, Pitch 0.95mm, Lead Span 2.7mm, IPC High Density)
footprint SOT-23-CH6_M (SOT23, 6-Leads, Body 2.9x1.6mm, Pitch 0.95mm, Lead Span 2.7mm, IPC Low Density)
pins: 1 VIN (power), 2 GND (power), 3 C-, 4 ~{SHDN} (in), 5 VOUT (power), 6 C+

## TC7660COA
designator U?
Charge Pump DC-to-DC Voltage Converter, 8-Pin SOIC 150mil, Commercial Temperature
footprint SOIC-OA8_N (SOIC, 8-Leads, Body 4.9x3.9mm, Pitch 1.27mm, IPC Medium Density)
footprint SOIC-OA8_L (SOIC, 8-Leads, Body 4.9x3.9mm, Pitch 1.27mm, IPC High Density)
footprint SOIC-OA8_M (SOIC, 8-Leads, Body 4.9x3.9mm, Pitch 1.27mm, IPC Low Density)
pins: 1 NC, 2 C+, 3 GND (power), 4 C-, 5 VOUT (power), 6 LV (in), 7 OSC (in), 8 VIN (power)

## TC7660COA713
designator U?
Charge Pump DC-to-DC Voltage Converter, 8-Pin SOIC 150mil, Commercial Temperature, Tape and Reel
footprint SOIC-OA8_N (SOIC, 8-Leads, Body 4.9x3.9mm, Pitch 1.27mm, IPC Medium Density)
footprint SOIC-OA8_L (SOIC, 8-Leads, Body 4.9x3.9mm, Pitch 1.27mm, IPC High Density)
footprint SOIC-OA8_M (SOIC, 8-Leads, Body 4.9x3.9mm, Pitch 1.27mm, IPC Low Density)
pins: 1 NC, 2 C+, 3 GND (power), 4 C-, 5 VOUT (power), 6 LV (in), 7 OSC (in), 8 VIN (power)

## TC7660CPA
designator U?
Charge Pump DC-to-DC Voltage Converter, 8-Pin PDIP, Commercial Temperature
footprint PDIP300-PA8 (DIP, 8-Leads, Row Spacing 7.62mm, Pitch 2.54mm, Body 9.5x6.6mm)
pins: 1 NC, 2 C+, 3 GND (power), 4 C-, 5 VOUT (power), 6 LV (in), 7 OSC (in), 8 VIN (power)

## TC7660EOA
designator U?
Charge Pump DC-to-DC Voltage Converter, 8-Pin SOIC 150mil, Industrial Temperature
footprint SOIC-OA8_N (SOIC, 8-Leads, Body 4.9x3.9mm, Pitch 1.27mm, IPC Medium Density)
footprint SOIC-OA8_L (SOIC, 8-Leads, Body 4.9x3.9mm, Pitch 1.27mm, IPC High Density)
footprint SOIC-OA8_M (SOIC, 8-Leads, Body 4.9x3.9mm, Pitch 1.27mm, IPC Low Density)
pins: 1 NC, 2 C+, 3 GND (power), 4 C-, 5 VOUT (power), 6 LV (in), 7 OSC (in), 8 VIN (power)

## TC7660EOA713
designator U?
Charge Pump DC-to-DC Voltage Converter, 8-Pin SOIC 150mil, Industrial Temperature, Tape and Reel
footprint SOIC-OA8_N (SOIC, 8-Leads, Body 4.9x3.9mm, Pitch 1.27mm, IPC Medium Density)
footprint SOIC-OA8_L (SOIC, 8-Leads, Body 4.9x3.9mm, Pitch 1.27mm, IPC High Density)
footprint SOIC-OA8_M (SOIC, 8-Leads, Body 4.9x3.9mm, Pitch 1.27mm, IPC Low Density)
pins: 1 NC, 2 C+, 3 GND (power), 4 C-, 5 VOUT (power), 6 LV (in), 7 OSC (in), 8 VIN (power)

## TC7660EPA
designator U?
Charge Pump DC-to-DC Voltage Converter, 8-Pin PDIP, Industrial Temperature
footprint PDIP300-PA8 (DIP, 8-Leads, Row Spacing 7.62mm, Pitch 2.54mm, Body 9.5x6.6mm)
pins: 1 NC, 2 C+, 3 GND (power), 4 C-, 5 VOUT (power), 6 LV (in), 7 OSC (in), 8 VIN (power)

## TC7660HCOA
designator U?
DC-to-DC Voltage Converter, 120kHz, 8-Pin SOIC 150mil, Commercial Temperature
footprint SOIC-OA8_N (SOIC, 8-Leads, Body 4.9x3.9mm, Pitch 1.27mm, IPC Medium Density)
footprint SOIC-OA8_L (SOIC, 8-Leads, Body 4.9x3.9mm, Pitch 1.27mm, IPC High Density)
footprint SOIC-OA8_M (SOIC, 8-Leads, Body 4.9x3.9mm, Pitch 1.27mm, IPC Low Density)
pins: 1 NC, 2 C+, 3 GND (power), 4 C-, 5 VOUT (power), 6 LV (in), 7 OSC (in), 8 VIN (power)

## TC7660HCOA713
designator U?
Charge Pump DC-to-DC Voltage Converter, 8-Pin SOIC 150mil, Commercial Temperature, Tape and Reel
footprint SOIC-OA8_N (SOIC, 8-Leads, Body 4.9x3.9mm, Pitch 1.27mm, IPC Medium Density)
footprint SOIC-OA8_L (SOIC, 8-Leads, Body 4.9x3.9mm, Pitch 1.27mm, IPC High Density)
footprint SOIC-OA8_M (SOIC, 8-Leads, Body 4.9x3.9mm, Pitch 1.27mm, IPC Low Density)
pins: 1 NC, 2 C+, 3 GND (power), 4 C-, 5 VOUT (power), 6 LV (in), 7 OSC (in), 8 VIN (power)

## TC7660HCPA
designator U?
DC-to-DC Voltage Converter, 120kHz, 8-Pin PDIP, Commercial Temperature
footprint PDIP300-PA8 (DIP, 8-Leads, Row Spacing 7.62mm, Pitch 2.54mm, Body 9.5x6.6mm)
pins: 1 NC, 2 C+, 3 GND (power), 4 C-, 5 VOUT (power), 6 LV (in), 7 OSC (in), 8 VIN (power)

## TC7660HEOA
designator U?
DC-to-DC Voltage Converter, 120kHz, 8-Pin SOIC 150mil, Industrial Temperature
footprint SOIC-OA8_N (SOIC, 8-Leads, Body 4.9x3.9mm, Pitch 1.27mm, IPC Medium Density)
footprint SOIC-OA8_L (SOIC, 8-Leads, Body 4.9x3.9mm, Pitch 1.27mm, IPC High Density)
footprint SOIC-OA8_M (SOIC, 8-Leads, Body 4.9x3.9mm, Pitch 1.27mm, IPC Low Density)
pins: 1 NC, 2 C+, 3 GND (power), 4 C-, 5 VOUT (power), 6 LV (in), 7 OSC (in), 8 VIN (power)

## TC7660HEOA713
designator U?
Charge Pump DC-to-DC Voltage Converter, 8-Pin SOIC 150mil, Industrial Temperature, Tape and Reel
footprint SOIC-OA8_N (SOIC, 8-Leads, Body 4.9x3.9mm, Pitch 1.27mm, IPC Medium Density)
footprint SOIC-OA8_L (SOIC, 8-Leads, Body 4.9x3.9mm, Pitch 1.27mm, IPC High Density)
footprint SOIC-OA8_M (SOIC, 8-Leads, Body 4.9x3.9mm, Pitch 1.27mm, IPC Low Density)
pins: 1 NC, 2 C+, 3 GND (power), 4 C-, 5 VOUT (power), 6 LV (in), 7 OSC (in), 8 VIN (power)

## TC7660HEPA
designator U?
DC-to-DC Voltage Converter, 120kHz, 8-Pin PDIP, Industrial Temperature
footprint PDIP300-PA8 (DIP, 8-Leads, Row Spacing 7.62mm, Pitch 2.54mm, Body 9.5x6.6mm)
pins: 1 NC, 2 C+, 3 GND (power), 4 C-, 5 VOUT (power), 6 LV (in), 7 OSC (in), 8 VIN (power)

## TC7660IJA
designator U?
Charge Pump DC-to-DC Voltage Converter, 8-Pin CERDIP 300mil, -25ºC to +85ºC
footprint CERDIP300-JA8 (DIP, 8-Leads, Row Spacing 7.62mm, Pitch 2.54mm, Body 9.8x6.7mm)
pins: 1 NC, 2 C+, 3 GND (power), 4 C-, 5 VOUT (power), 6 LV (in), 7 OSC (in), 8 VIN (power)

## TC7660MJA
designator U?
Charge Pump DC-to-DC Voltage Converter, 8-Pin CERDIP 300mil, -55ºC to +125ºC
footprint CERDIP300-JA8 (DIP, 8-Leads, Row Spacing 7.62mm, Pitch 2.54mm, Body 9.8x6.7mm)
pins: 1 NC, 2 C+, 3 GND (power), 4 C-, 5 VOUT (power), 6 LV (in), 7 OSC (in), 8 VIN (power)

## TC7660SCOA
designator U?
Super Charge Pump DC-to-DC Voltage Converter, 10kHz, 45kHz, 8-Pin SOIC 150mil, Commercial Temperature
footprint SOIC-OA8_N (SOIC, 8-Leads, Body 4.9x3.9mm, Pitch 1.27mm, IPC Medium Density)
footprint SOIC-OA8_L (SOIC, 8-Leads, Body 4.9x3.9mm, Pitch 1.27mm, IPC High Density)
footprint SOIC-OA8_M (SOIC, 8-Leads, Body 4.9x3.9mm, Pitch 1.27mm, IPC Low Density)
pins: 1 BOOST (in), 2 C+, 3 GND (power), 4 C-, 5 VOUT (power), 6 LV (in), 7 OSC (in), 8 VIN (power)

## TC7660SCOA713
designator U?
Super Charge Pump DC-to-DC Voltage Converter, 10kHz, 45kHz, 8-Pin SOIC 150mil, Commercial Temperature, Tape and Reel
footprint SOIC-OA8_N (SOIC, 8-Leads, Body 4.9x3.9mm, Pitch 1.27mm, IPC Medium Density)
footprint SOIC-OA8_L (SOIC, 8-Leads, Body 4.9x3.9mm, Pitch 1.27mm, IPC High Density)
footprint SOIC-OA8_M (SOIC, 8-Leads, Body 4.9x3.9mm, Pitch 1.27mm, IPC Low Density)
pins: 1 BOOST (in), 2 C+, 3 GND (power), 4 C-, 5 VOUT (power), 6 LV (in), 7 OSC (in), 8 VIN (power)

## TC7660SCPA
designator U?
Super Charge Pump DC-to-DC Voltage Converter, 10kHz, 45kHz, 8-Pin PDIP, Commercial Temperature
footprint PDIP300-PA8 (DIP, 8-Leads, Row Spacing 7.62mm, Pitch 2.54mm, Body 9.5x6.6mm)
pins: 1 BOOST (in), 2 C+, 3 GND (power), 4 C-, 5 VOUT (power), 6 LV (in), 7 OSC (in), 8 VIN (power)

## TC7660SEJA
designator U?
Super Charge Pump DC-to-DC Voltage Converter, 10kHz, 45kHz, 8-Pin CERDIP 300mil, Industrial Temperature; ComponentAvailability: Unknown. Contact manufacturer to determine status.
footprint CERDIP300-JA8 (DIP, 8-Leads, Row Spacing 7.62mm, Pitch 2.54mm, Body 9.8x6.7mm)
pins: 1 BOOST (in), 2 C+, 3 GND (power), 4 C-, 5 VOUT (power), 6 LV (in), 7 OSC (in), 8 VIN (power)

## TC7660SEOA
designator U?
Super Charge Pump DC-to-DC Voltage Converter, 10kHz, 45kHz, 8-Pin SOIC 150mil, Industrial Temperature
footprint SOIC-OA8_N (SOIC, 8-Leads, Body 4.9x3.9mm, Pitch 1.27mm, IPC Medium Density)
footprint SOIC-OA8_L (SOIC, 8-Leads, Body 4.9x3.9mm, Pitch 1.27mm, IPC High Density)
footprint SOIC-OA8_M (SOIC, 8-Leads, Body 4.9x3.9mm, Pitch 1.27mm, IPC Low Density)
pins: 1 BOOST (in), 2 C+, 3 GND (power), 4 C-, 5 VOUT (power), 6 LV (in), 7 OSC (in), 8 VIN (power)

## TC7660SEOA713
designator U?
Super Charge Pump DC-to-DC Voltage Converter, 10kHz, 45kHz, 8-Pin SOIC 150mil, Industrial Temperature, Tape and Reel
footprint SOIC-OA8_N (SOIC, 8-Leads, Body 4.9x3.9mm, Pitch 1.27mm, IPC Medium Density)
footprint SOIC-OA8_L (SOIC, 8-Leads, Body 4.9x3.9mm, Pitch 1.27mm, IPC High Density)
footprint SOIC-OA8_M (SOIC, 8-Leads, Body 4.9x3.9mm, Pitch 1.27mm, IPC Low Density)
pins: 1 BOOST (in), 2 C+, 3 GND (power), 4 C-, 5 VOUT (power), 6 LV (in), 7 OSC (in), 8 VIN (power)

## TC7660SEPA
designator U?
Super Charge Pump DC-to-DC Voltage Converter, 10kHz, 45kHz, 8-Pin PDIP, Industrial Temperature
footprint PDIP300-PA8 (DIP, 8-Leads, Row Spacing 7.62mm, Pitch 2.54mm, Body 9.5x6.6mm)
pins: 1 BOOST (in), 2 C+, 3 GND (power), 4 C-, 5 VOUT (power), 6 LV (in), 7 OSC (in), 8 VIN (power)

## TC7660SMJA
designator U?
Super Charge Pump DC-to-DC Voltage Converter, 10kHz, 45kHz, 8-Pin CERDIP 300mil, -55ºC to +125ºC; ComponentAvailability: Unknown. Contact manufacturer to determine status.
footprint CERDIP300-JA8 (DIP, 8-Leads, Row Spacing 7.62mm, Pitch 2.54mm, Body 9.8x6.7mm)
pins: 1 BOOST (in), 2 C+, 3 GND (power), 4 C-, 5 VOUT (power), 6 LV (in), 7 OSC (in), 8 VIN (power)

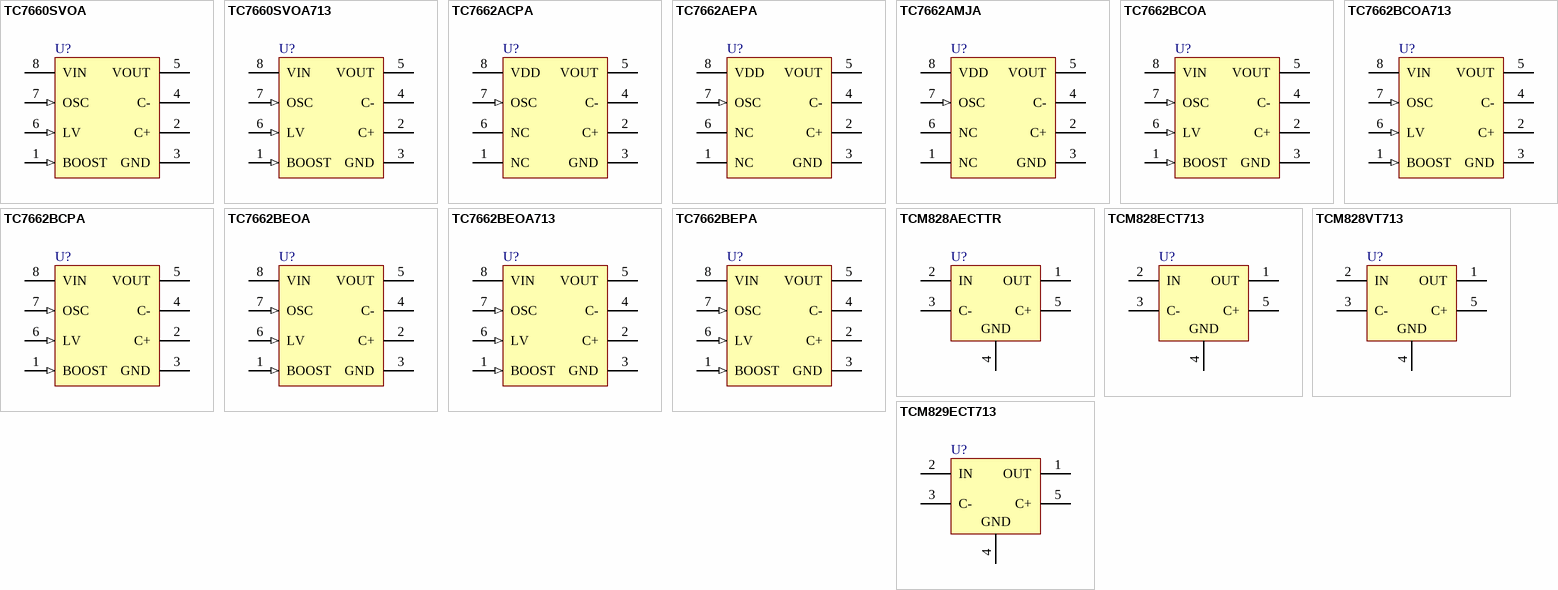
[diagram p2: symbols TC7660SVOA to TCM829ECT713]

## TC7660SVOA
designator U?
Super Charge Pump DC-to-DC Voltage Converter, 10kHz, 45kHz, 8-Pin SOIC 150mil, Extended Temperature
footprint SOIC-OA8_N (SOIC, 8-Leads, Body 4.9x3.9mm, Pitch 1.27mm, IPC Medium Density)
footprint SOIC-OA8_L (SOIC, 8-Leads, Body 4.9x3.9mm, Pitch 1.27mm, IPC High Density)
footprint SOIC-OA8_M (SOIC, 8-Leads, Body 4.9x3.9mm, Pitch 1.27mm, IPC Low Density)
pins: 1 BOOST (in), 2 C+, 3 GND (power), 4 C-, 5 VOUT (power), 6 LV (in), 7 OSC (in), 8 VIN (power)

## TC7660SVOA713
designator U?
Super Charge Pump DC-to-DC Voltage Converter, 10kHz, 45kHz, 8-Pin SOIC 150mil, Extended Temperature, Tape and Reel
footprint SOIC-OA8_N (SOIC, 8-Leads, Body 4.9x3.9mm, Pitch 1.27mm, IPC Medium Density)
footprint SOIC-OA8_L (SOIC, 8-Leads, Body 4.9x3.9mm, Pitch 1.27mm, IPC High Density)
footprint SOIC-OA8_M (SOIC, 8-Leads, Body 4.9x3.9mm, Pitch 1.27mm, IPC Low Density)
pins: 1 BOOST (in), 2 C+, 3 GND (power), 4 C-, 5 VOUT (power), 6 LV (in), 7 OSC (in), 8 VIN (power)

## TC7662ACPA
designator U?
Super Charge Pump DC-to-DC Voltage Converter, 12kHz, 8-Pin PDIP, Commercial Temperature
footprint PDIP300-PA8 (DIP, 8-Leads, Row Spacing 7.62mm, Pitch 2.54mm, Body 9.5x6.6mm)
pins: 1 NC, 2 C+, 3 GND (power), 4 C-, 5 VOUT (power), 6 NC, 7 OSC (in), 8 VDD (power)

## TC7662AEPA
designator U?
Super Charge Pump DC-to-DC Voltage Converter, 12kHz, 8-Pin PDIP, Industrial Temperature
footprint PDIP300-PA8 (DIP, 8-Leads, Row Spacing 7.62mm, Pitch 2.54mm, Body 9.5x6.6mm)
pins: 1 NC, 2 C+, 3 GND (power), 4 C-, 5 VOUT (power), 6 NC, 7 OSC (in), 8 VDD (power)

## TC7662AMJA
designator U?
Super Charge Pump DC-to-DC Voltage Converter, 12kHz, 8-Pin CERDIP 300mil, -55ºC to +125ºC
footprint CERDIP300-JA8 (DIP, 8-Leads, Row Spacing 7.62mm, Pitch 2.54mm, Body 9.8x6.7mm)
pins: 1 NC, 2 C+, 3 GND (power), 4 C-, 5 VOUT (power), 6 NC, 7 OSC (in), 8 VDD (power)

## TC7662BCOA
designator U?
Charge Pump DC-to-DC Voltage Converter, 10kHz, 35kHz, 8-Pin SOIC 150mil, Commercial Temperature
footprint SOIC-OA8_N (SOIC, 8-Leads, Body 4.9x3.9mm, Pitch 1.27mm, IPC Medium Density)
footprint SOIC-OA8_L (SOIC, 8-Leads, Body 4.9x3.9mm, Pitch 1.27mm, IPC High Density)
footprint SOIC-OA8_M (SOIC, 8-Leads, Body 4.9x3.9mm, Pitch 1.27mm, IPC Low Density)
pins: 1 BOOST (in), 2 C+, 3 GND (power), 4 C-, 5 VOUT (power), 6 LV (in), 7 OSC (in), 8 VIN (power)

## TC7662BCOA713
designator U?
Charge Pump DC-to-DC Voltage Converter, 10kHz, 35kHz, 8-Pin SOIC 150mil, Commercial Temperature, Tape and Reel
footprint SOIC-OA8_N (SOIC, 8-Leads, Body 4.9x3.9mm, Pitch 1.27mm, IPC Medium Density)
footprint SOIC-OA8_L (SOIC, 8-Leads, Body 4.9x3.9mm, Pitch 1.27mm, IPC High Density)
footprint SOIC-OA8_M (SOIC, 8-Leads, Body 4.9x3.9mm, Pitch 1.27mm, IPC Low Density)
pins: 1 BOOST (in), 2 C+, 3 GND (power), 4 C-, 5 VOUT (power), 6 LV (in), 7 OSC (in), 8 VIN (power)

## TC7662BCPA
designator U?
Charge Pump DC-to-DC Voltage Converter, 10kHz, 35kHz, 8-Pin PDIP, Commercial Temperature
footprint PDIP300-PA8 (DIP, 8-Leads, Row Spacing 7.62mm, Pitch 2.54mm, Body 9.5x6.6mm)
pins: 1 BOOST (in), 2 C+, 3 GND (power), 4 C-, 5 VOUT (power), 6 LV (in), 7 OSC (in), 8 VIN (power)

## TC7662BEOA
designator U?
Charge Pump DC-to-DC Voltage Converter, 10kHz, 35kHz, 8-Pin SOIC 150mil, Industrial Temperature
footprint SOIC-OA8_N (SOIC, 8-Leads, Body 4.9x3.9mm, Pitch 1.27mm, IPC Medium Density)
footprint SOIC-OA8_L (SOIC, 8-Leads, Body 4.9x3.9mm, Pitch 1.27mm, IPC High Density)
footprint SOIC-OA8_M (SOIC, 8-Leads, Body 4.9x3.9mm, Pitch 1.27mm, IPC Low Density)
pins: 1 BOOST (in), 2 C+, 3 GND (power), 4 C-, 5 VOUT (power), 6 LV (in), 7 OSC (in), 8 VIN (power)

## TC7662BEOA713
designator U?
Charge Pump DC-to-DC Voltage Converter, 10kHz, 35kHz, 8-Pin SOIC 150mil, Industrial Temperature, Tape and Reel
footprint SOIC-OA8_N (SOIC, 8-Leads, Body 4.9x3.9mm, Pitch 1.27mm, IPC Medium Density)
footprint SOIC-OA8_L (SOIC, 8-Leads, Body 4.9x3.9mm, Pitch 1.27mm, IPC High Density)
footprint SOIC-OA8_M (SOIC, 8-Leads, Body 4.9x3.9mm, Pitch 1.27mm, IPC Low Density)
pins: 1 BOOST (in), 2 C+, 3 GND (power), 4 C-, 5 VOUT (power), 6 LV (in), 7 OSC (in), 8 VIN (power)

## TC7662BEPA
designator U?
Charge Pump DC-to-DC Voltage Converter, 10kHz, 35kHz, 8-Pin PDIP, Industrial Temperature
footprint PDIP300-PA8 (DIP, 8-Leads, Row Spacing 7.62mm, Pitch 2.54mm, Body 9.5x6.6mm)
pins: 1 BOOST (in), 2 C+, 3 GND (power), 4 C-, 5 VOUT (power), 6 LV (in), 7 OSC (in), 8 VIN (power)

## TCM828AECTTR
designator U?
50µA Switched Capacitor Voltage Converter, 5-Pin SOT-23, Industrial Temperature, Tape and Reel; ComponentAvailability: Unknown. Contact manufacturer to determine status.
footprint SOT-23-CT5_N (SOT23, 5-Leads, Body 2.9x1.6mm, Pitch 0.95mm, Lead Span 2.7mm, IPC Medium Density)
footprint SOT-23-CT5_L (SOT23, 5-Leads, Body 2.9x1.6mm, Pitch 0.95mm, Lead Span 2.7mm, IPC High Density)
footprint SOT-23-CT5_M (SOT23, 5-Leads, Body 2.9x1.6mm, Pitch 0.95mm, Lead Span 2.7mm, IPC Low Density)
pins: 1 OUT (power), 2 IN (power), 3 C-, 4 GND (power), 5 C+

## TCM828ECT713
designator U?
50µA Switched Capacitor Voltage Converter, 5-Pin SOT-23, Industrial Temperature, Tape and Reel
footprint SOT-23-CT5_N (SOT23, 5-Leads, Body 2.9x1.6mm, Pitch 0.95mm, Lead Span 2.7mm, IPC Medium Density)
footprint SOT-23-CT5_L (SOT23, 5-Leads, Body 2.9x1.6mm, Pitch 0.95mm, Lead Span 2.7mm, IPC High Density)
footprint SOT-23-CT5_M (SOT23, 5-Leads, Body 2.9x1.6mm, Pitch 0.95mm, Lead Span 2.7mm, IPC Low Density)
pins: 1 OUT (power), 2 IN (power), 3 C-, 4 GND (power), 5 C+

## TCM828VT713
designator U?
50µA Switched Capacitor Voltage Converter, 5-Pin SOT-23, Extended Temperature, Tape and Reel
footprint SOT-23-CT5_N (SOT23, 5-Leads, Body 2.9x1.6mm, Pitch 0.95mm, Lead Span 2.7mm, IPC Medium Density)
footprint SOT-23-CT5_L (SOT23, 5-Leads, Body 2.9x1.6mm, Pitch 0.95mm, Lead Span 2.7mm, IPC High Density)
footprint SOT-23-CT5_M (SOT23, 5-Leads, Body 2.9x1.6mm, Pitch 0.95mm, Lead Span 2.7mm, IPC Low Density)
pins: 1 OUT (power), 2 IN (power), 3 C-, 4 GND (power), 5 C+

## TCM829ECT713
designator U?
115µA Switched Capacitor Voltage Converter, 5-Pin SOT-23, Industrial Temperature, Tape and Reel
footprint SOT-23-CT5_N (SOT23, 5-Leads, Body 2.9x1.6mm, Pitch 0.95mm, Lead Span 2.7mm, IPC Medium Density)
footprint SOT-23-CT5_L (SOT23, 5-Leads, Body 2.9x1.6mm, Pitch 0.95mm, Lead Span 2.7mm, IPC High Density)
footprint SOT-23-CT5_M (SOT23, 5-Leads, Body 2.9x1.6mm, Pitch 0.95mm, Lead Span 2.7mm, IPC Low Density)
pins: 1 OUT (power), 2 IN (power), 3 C-, 4 GND (power), 5 C+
